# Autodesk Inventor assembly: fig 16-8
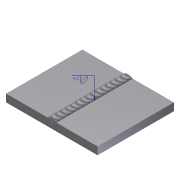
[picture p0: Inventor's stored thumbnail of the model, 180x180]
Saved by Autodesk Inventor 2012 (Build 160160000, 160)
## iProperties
Created: 2004-07
Part Number: fig 16-8
Document SubType Name: Weldment
Designer: CADCIM Technologies
Manufacturer: Standard
Standards Organization: Custom
Author: CADCIM Technologies
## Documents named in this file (2)
- C:\Users\CadCim\Documents\SAILESH\inventor-2011-fact-prt\c16-inv-2011-prt\c16_inv_2012_prt\fig 16-8\fig 16-8.iam
- C:\Users\CadCim\Documents\SAILESH\inventor-2011-fact-prt\c16-inv-2011-prt\fig-16-8\Plate.ipt
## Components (2 placed, 1 different names)
1. Plate:1 — Mate:1, Flush:1, Flush:2
2. Plate:2 — Mate:1, Flush:1, Flush:2
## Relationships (3: Flush 2, Mate 1)
- Mate:1: Plate:1 ↔ Plate:2
- Flush:1: Plate:1 ↔ Plate:2
- Flush:2: Plate:1 ↔ Plate:2
